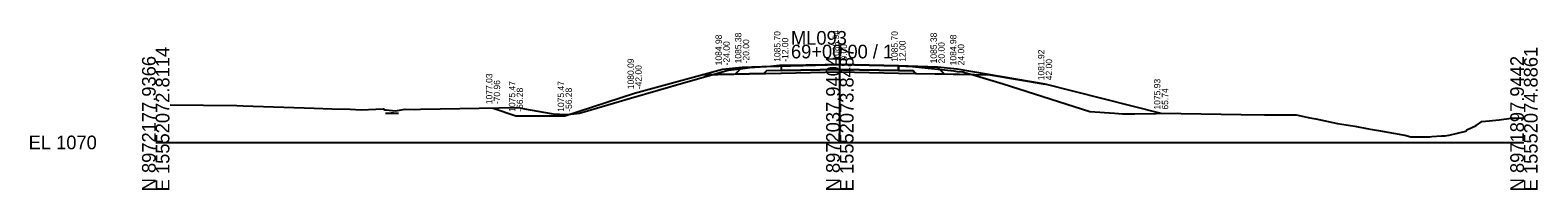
# Model space of a CAD drawing. Extents: x -26 to 14283, y -10 to 28.
# Drawn here: x 3974.3 to 4282.8, y -9.7 to 23 of the extents above; entities that cross this region are included whole.
import ezdxf

# ---------------------------------------------------------------- set-up
doc = ezdxf.new("R2010")
doc.units = 0
for name, color, linetype in [('Default', 7, 'Continuous'), ('dsn3DCenterLine', 7, 'Continuous'), ('dsn3DDitchBack', 7, 'Continuous'), ('dsn3DDitchFront', 7, 'Continuous'), ('dsn3DForeSlopeBarnRoofPoint', 7, 'Continuous'), ('dsn3DForeSlopeBreakLine', 7, 'Continuous'), ('dsn3DGroundLineIntercept', 7, 'Continuous'), ('dsn3DPavementTop', 7, 'Continuous'), ('dsn3DShoulderTop', 7, 'Continuous'), ('dsn3DSubgradeBreakLine', 7, 'Continuous'), ('dsn3DSubgradeHingePoint', 7, 'Continuous'), ('dsnGeopakCellCrossSection', 7, 'Continuous'), ('dsnXSEarthwork', 7, 'Continuous'), ('dsnXsExistingGround', 7, 'Continuous'), ('dsnXsPCCPavement', 7, 'Continuous'), ('dsnXsShldrEarthFill', 7, 'Continuous'), ('dsnXsShldrGranular', 7, 'Continuous'), ('dsnXsSideSlopes', 7, 'Continuous'), ('dsnXsSubbase', 7, 'Continuous'), ('dsnXsTextOffsetElevFinGrd', 7, 'Continuous'), ('SurDrainage', 7, 'Continuous'), ('SurSurveyPoints', 7, 'Continuous')]:
    doc.layers.add(name, color=color, linetype=linetype)

msp = doc.modelspace()

# ---------------------------------------------------------------- linework, layer by layer
at = {"layer": 'Default'}
for points in [[(4120, 15.38), (4140, 15.94), (4140, 15.94), (4152, 15.7), (4160, 15.38)], [(4111.81, 13.84), (4111.81, 13.84), (4128, 14.2), (4140, 14.44), (4152, 14.2), (4170.7, 13.84), (4182, 11.92)]]:
    msp.add_lwpolyline(points, dxfattribs=at)
at = {"layer": 'dsnGeopakCellCrossSection'}
for p, q in [((4140, 0), (4140, 20)), ((4000, 0), (4140, 0)), ((4140, 0), (4280, 0))]:
    msp.add_line(p, q, dxfattribs=at)
at = {"layer": 'dsnXSEarthwork'}
msp.add_lwpolyline([(4120, 15.38), (4128, 15.7), (4140, 15.94), (4152, 15.7), (4160, 15.38)], dxfattribs=at)
at = {"layer": 'dsnXsExistingGround'}
msp.add_lwpolyline([(4002.97, 7.72), (4016.63, 7.53), (4017.91, 7.48), (4032.44, 7.03), (4036.01, 6.91), (4039.79, 6.84), (4042.05, 6.69), (4046.57, 6.86), (4046.92, 6.68), (4047.19, 6.66), (4049.04, 6.5), (4051.02, 6.84), (4053.04, 6.76), (4054.2, 6.78), (4074.22, 7.12), (4075.46, 6.9), (4080.92, 5.91), (4081.33, 5.88), (4083.92, 5.69), (4084.38, 5.74), (4086.73, 6.01), (4092.54, 7.72), (4097.19, 9.06), (4108.48, 12.35), (4117.18, 14.8), (4120.14, 15.16), (4121.6, 15.33), (4125.84, 15.64), (4127.62, 15.78), (4138.35, 15.92), (4140.07, 15.94), (4151.22, 15.73), (4151.69, 15.72), (4151.81, 15.72), (4152.14, 15.7), (4154.89, 15.54), (4159.39, 15.07), (4161.45, 14.89), (4163.34, 14.68), (4163.98, 14.55), (4165.13, 14.45), (4165.22, 14.43), (4165.36, 14.38), (4165.52, 14.33), (4165.53, 14.32), (4166.78, 13.97), (4167.96, 13.6), (4173.41, 11.97), (4191.15, 6.32), (4196.22, 5.97), (4197.84, 5.84), (4200.36, 5.88), (4209.11, 5.96), (4209.84, 5.94), (4222.16, 5.7), (4226.9, 5.63), (4232.64, 5.66), (4233.4, 5.63), (4236.15, 5.01), (4237.41, 4.8), (4241.86, 3.88), (4245.41, 3.32), (4248.2, 2.82), (4250.2, 2.44), (4255.19, 1.56), (4255.65, 1.46), (4256.83, 1.16), (4257.72, 1.14), (4260.73, 1.15), (4261.14, 1.19), (4263.13, 1.33), (4263.66, 1.37), (4263.84, 1.38), (4264.6, 1.48), (4264.67, 1.48), (4268.08, 2.28), (4268.3, 2.6), (4270.19, 3.48), (4271.39, 4.32), (4272.85, 4.4), (4274.92, 4.65), (4277.41, 4.94), (4280, 5.04)], dxfattribs=at)
at = {"layer": 'dsnXsPCCPavement'}
msp.add_lwpolyline([(4128, 15.7), (4128, 15.7), (4128, 14.7), (4128, 14.7), (4128, 14.7), (4140, 14.94), (4152, 14.7), (4152, 14.7), (4152, 14.7), (4152, 15.7), (4152, 15.7), (4140, 15.94), (4128, 15.7)], dxfattribs=at)
at = {"layer": 'dsnXsShldrEarthFill'}
for points in [[(4118.61, 13.99), (4111.81, 13.84)], [(4161.36, 14.02), (4170.7, 13.84)]]:
    msp.add_lwpolyline(points, dxfattribs=at)
at = {"layer": 'dsnXsShldrGranular'}
for points in [[(4120, 15.38), (4128, 15.7), (4128, 14.7), (4128, 14.7), (4125, 14.64), (4125, 14.64), (4124.48, 14.12), (4124.48, 14.12), (4124.48, 14.12), (4118.61, 13.99), (4118.61, 13.99), (4120, 15.38), (4120, 15.38)], [(4160, 15.38), (4152, 15.7), (4152, 14.7), (4152, 14.7), (4155, 14.64), (4155, 14.64), (4155.51, 14.13), (4155.51, 14.13), (4155.51, 14.13), (4161.36, 14.02), (4161.36, 14.02), (4160, 15.38), (4160, 15.38)]]:
    msp.add_lwpolyline(points, dxfattribs=at)
at = {"layer": 'dsnXsSideSlopes'}
for points in [[(4069.04, 7.03), (4069.04, 7.03), (4073.72, 5.47), (4073.72, 5.47), (4083.72, 5.47), (4083.72, 5.47), (4098, 10.09), (4116, 14.98), (4116, 14.98), (4116, 14.98), (4120, 15.38)], [(4205.74, 5.93), (4205.74, 5.93), (4182, 11.92), (4164, 14.98), (4164, 14.98), (4164, 14.98), (4160, 15.38)]]:
    msp.add_lwpolyline(points, dxfattribs=at)
at = {"layer": 'dsnXsSubbase'}
msp.add_lwpolyline([(4124.48, 14.12), (4124.48, 14.12), (4124.48, 14.12), (4128, 14.2), (4128, 14.2), (4140, 14.44), (4152, 14.2), (4152, 14.2), (4152, 14.2), (4155.51, 14.13), (4155.51, 14.13), (4155, 14.64), (4155, 14.64), (4152, 14.7), (4152, 14.7), (4140, 14.94), (4128, 14.7), (4128, 14.7), (4125, 14.64), (4125, 14.64), (4124.48, 14.12)], dxfattribs=at)
at = {"layer": 'SurDrainage'}
for points in [[(4047.05, 5.99), (4049.67, 5.99)], [(4048.17, 6.04), (4048.71, 6.04)]]:
    msp.add_lwpolyline(points, dxfattribs=at)
at = {"layer": 'SurSurveyPoints'}
msp.add_lwpolyline([(4127.36, 15.77), (4127.87, 15.77)], dxfattribs=at)

# ---------------------------------------------------------------- texts
msp.add_text('-', height=0.0001).set_placement((4000, 0))
at = {"layer": 'dsn3DCenterLine'}
msp.add_text('X', height=0.00781, dxfattribs=at).set_placement((4140, 15.94))
at = {"layer": 'dsn3DDitchBack'}
msp.add_text('X', height=0.00781, dxfattribs=at).set_placement((4073.72, 5.47))
at = {"layer": 'dsn3DDitchFront'}
msp.add_text('X', height=0.00781, dxfattribs=at).set_placement((4083.72, 5.47))
at = {"layer": 'dsn3DForeSlopeBarnRoofPoint'}
for p in [(4098, 10.08), (4182, 11.92)]:
    msp.add_text('X', height=0.00781, dxfattribs=at).set_placement(p)
at = {"layer": 'dsn3DForeSlopeBreakLine'}
for p in [(4116, 14.98), (4164, 14.98)]:
    msp.add_text('X', height=0.00781, dxfattribs=at).set_placement(p)
at = {"layer": 'dsn3DGroundLineIntercept'}
for p in [(4069.03, 7.03), (4205.73, 5.93)]:
    msp.add_text('X', height=0.00781, dxfattribs=at).set_placement(p)
at = {"layer": 'dsn3DPavementTop'}
for p in [(4128, 15.7), (4152, 15.7)]:
    msp.add_text('X', height=0.00781, dxfattribs=at).set_placement(p)
at = {"layer": 'dsn3DShoulderTop'}
for p in [(4120, 15.38), (4160, 15.38)]:
    msp.add_text('X', height=0.00781, dxfattribs=at).set_placement(p)
at = {"layer": 'dsn3DSubgradeBreakLine'}
for p in [(4128, 14.2), (4140, 14.44), (4152, 14.2)]:
    msp.add_text('X', height=0.00781, dxfattribs=at).set_placement(p)
at = {"layer": 'dsn3DSubgradeHingePoint'}
for p in [(4111.8, 13.84), (4170.7, 13.84)]:
    msp.add_text('X', height=0.00781, dxfattribs=at).set_placement(p)
at = {"layer": 'dsnGeopakCellCrossSection'}
for s, p in [('ML093', (4130, 20)), ('69+00.00 / 1', (4130, 17.2)), ('EL 1070', (3974, -1.4))]:
    msp.add_text(s, height=2.8, dxfattribs=at).set_placement(p)
for s, p in [('E 15552072.8114', (4002.8, -10)), ('E 15552073.8487', (4142.8, -10)), ('E 15552074.8861', (4282.8, -10)), ('N 8972177.9366', (4000, -10)), ('N 8972037.9404', (4140, -10)), ('N 8971897.9442', (4280, -10))]:
    msp.add_text(s, height=2.8, rotation=90, dxfattribs=at).set_placement(p)
at = {"layer": 'dsnXsTextOffsetElevFinGrd'}
for s, p in [('1084.98', (4115.85, 15.78)), ('1085.38', (4119.85, 16.18)), ('1085.70', (4127.85, 16.5)), ('1085.70', (4127.85, 16.5)), ('1085.94', (4139.85, 16.74)), ('1085.70', (4151.85, 16.5)), ('1085.38', (4159.85, 16.18)), ('1084.98', (4163.85, 15.78)), ('-24.00', (4117.45, 15.78)), ('-20.00', (4121.45, 16.18)), ('-12.00', (4129.45, 16.5)), ('-12.00', (4129.45, 16.5)), ('0.00', (4141.45, 16.74)), ('12.00', (4153.45, 16.5)), ('20.00', (4161.45, 16.18)), ('24.00', (4165.45, 15.78)), ('1081.92', (4181.85, 12.72)), ('1080.09', (4097.85, 10.89)), ('-42.00', (4099.45, 10.89)), ('42.00', (4183.45, 12.72)), ('1077.03', (4068.89, 7.83)), ('-70.96', (4070.49, 7.83)), ('1075.47', (4073.57, 6.27)), ('1075.47', (4083.57, 6.27)), ('1075.47', (4083.57, 6.27)), ('1075.93', (4205.59, 6.73)), ('1075.93', (4205.59, 6.73)), ('-66.28', (4075.17, 6.27)), ('-56.28', (4085.17, 6.27)), ('-56.28', (4085.17, 6.27)), ('65.74', (4207.19, 6.73)), ('65.74', (4207.19, 6.73))]:
    msp.add_text(s, height=1.3, rotation=90, dxfattribs=at).set_placement(p)

doc.saveas('drawing.dxf')
